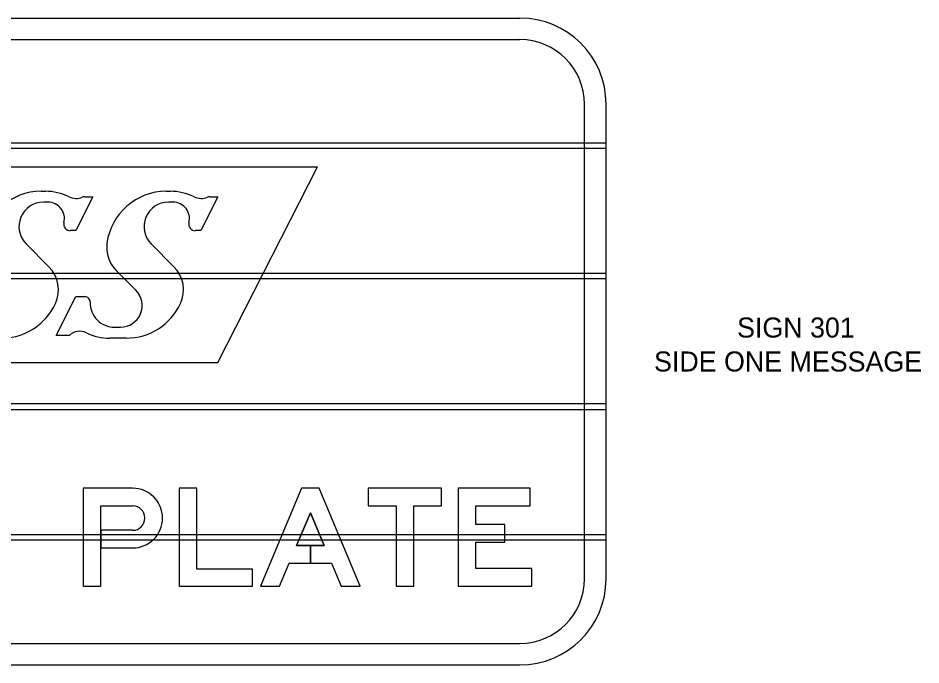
# Model space of a CAD drawing. Extents: x 319706 to 320346, y 1621790 to 1622121.
# Drawn here: x 319957 to 320020, y 1621942.3 to 1621987.5 of the extents above; entities that cross this region are included whole.
import ezdxf

# ---------------------------------------------------------------- set-up
doc = ezdxf.new("R2010")
doc.units = 0
for name, color, linetype in [('1', 7, 'Continuous'), ('40', 7, 'Continuous'), ('GSBWFill', 7, 'Continuous'), ('GSColorFill', 7, 'Continuous'), ('GSOutline', 7, 'Continuous'), ('SignPanel', 7, 'Continuous')]:
    doc.layers.add(name, color=color, linetype=linetype)

msp = doc.modelspace()

# ---------------------------------------------------------------- linework, layer by layer
at = {"layer": 'GSBWFill'}
msp.add_line((319962.741, 1621953.413), (319964.965, 1621953.413), dxfattribs=at)
for points in [[(319964.965, 1621954.644), (319961.51, 1621954.644), (319961.51, 1621947.803), (319962.741, 1621947.803), (319962.741, 1621953.413)], [(319964.965, 1621951.703), (319962.741, 1621951.703), (319962.741, 1621950.471), (319964.965, 1621950.471)]]:
    msp.add_lwpolyline(points, dxfattribs=at)
for points in [[(319973.345, 1621947.803), (319973.345, 1621949), (319969.446, 1621949), (319969.446, 1621954.644), (319968.214, 1621954.644), (319968.214, 1621947.803)], [(319978.343, 1621950.642), (319977.382, 1621950.642), (319977.382, 1621949.411), (319978.86, 1621949.411), (319979.535, 1621947.803), (319980.871, 1621947.803), (319977.998, 1621954.644), (319976.766, 1621954.644), (319973.893, 1621947.803), (319975.228, 1621947.803), (319975.904, 1621949.411), (319977.382, 1621949.411), (319977.382, 1621950.642), (319976.421, 1621950.642), (319977.382, 1621952.93)], [(319981.418, 1621953.413), (319983.368, 1621953.413), (319983.368, 1621947.803), (319984.6, 1621947.803), (319984.6, 1621953.413), (319986.55, 1621953.413), (319986.55, 1621954.644), (319981.418, 1621954.644)], [(319992.844, 1621949.034), (319988.944, 1621949.034), (319988.944, 1621950.874), (319990.962, 1621950.874), (319990.962, 1621952.106), (319988.944, 1621952.106), (319988.944, 1621953.413), (319992.741, 1621953.413), (319992.741, 1621954.644), (319987.713, 1621954.644), (319987.713, 1621947.803), (319992.844, 1621947.803)]]:
    msp.add_lwpolyline(points, close=True, dxfattribs=at)
for major_axis in [(0, 2.087), (0, 0.855)]:
    msp.add_ellipse((319964.965, 1621952.558), major_axis=major_axis, ratio=0.999994, start_param=3.141593, end_param=6.283185, dxfattribs=at)
at = {"layer": 'GSColorFill'}
msp.add_line((319962.741, 1621953.413), (319964.965, 1621953.413), dxfattribs=at)
for points in [[(319964.965, 1621954.644), (319961.51, 1621954.644), (319961.51, 1621947.803), (319962.741, 1621947.803), (319962.741, 1621953.413)], [(319964.965, 1621951.703), (319962.741, 1621951.703), (319962.741, 1621950.471), (319964.965, 1621950.471)]]:
    msp.add_lwpolyline(points, dxfattribs=at)
for points in [[(319973.345, 1621947.803), (319973.345, 1621949), (319969.446, 1621949), (319969.446, 1621954.644), (319968.214, 1621954.644), (319968.214, 1621947.803)], [(319978.343, 1621950.642), (319977.382, 1621950.642), (319977.382, 1621949.411), (319978.86, 1621949.411), (319979.535, 1621947.803), (319980.871, 1621947.803), (319977.998, 1621954.644), (319976.766, 1621954.644), (319973.893, 1621947.803), (319975.228, 1621947.803), (319975.904, 1621949.411), (319977.382, 1621949.411), (319977.382, 1621950.642), (319976.421, 1621950.642), (319977.382, 1621952.93)], [(319981.418, 1621953.413), (319983.368, 1621953.413), (319983.368, 1621947.803), (319984.6, 1621947.803), (319984.6, 1621953.413), (319986.55, 1621953.413), (319986.55, 1621954.644), (319981.418, 1621954.644)], [(319992.844, 1621949.034), (319988.944, 1621949.034), (319988.944, 1621950.874), (319990.962, 1621950.874), (319990.962, 1621952.106), (319988.944, 1621952.106), (319988.944, 1621953.413), (319992.741, 1621953.413), (319992.741, 1621954.644), (319987.713, 1621954.644), (319987.713, 1621947.803), (319992.844, 1621947.803)]]:
    msp.add_lwpolyline(points, close=True, dxfattribs=at)
for major_axis in [(0, 2.087), (0, 0.855)]:
    msp.add_ellipse((319964.965, 1621952.558), major_axis=major_axis, ratio=0.999994, start_param=3.141593, end_param=6.283185, dxfattribs=at)
at = {"layer": 'GSOutline'}
for p, q in [((319962.741, 1621953.413), (319964.965, 1621953.413)), ((319962.741, 1621950.471), (319964.965, 1621950.471))]:
    msp.add_line(p, q, dxfattribs=at)
for points in [[(319964.965, 1621954.644), (319961.51, 1621954.644), (319961.51, 1621947.803), (319962.741, 1621947.803), (319962.741, 1621950.471)], [(319964.965, 1621951.703), (319962.741, 1621951.703), (319962.741, 1621953.413)]]:
    msp.add_lwpolyline(points, dxfattribs=at)
for points in [[(319973.345, 1621947.803), (319973.345, 1621949), (319969.446, 1621949), (319969.446, 1621954.644), (319968.214, 1621954.644), (319968.214, 1621947.803)], [(319975.904, 1621949.411), (319978.86, 1621949.411), (319979.535, 1621947.803), (319980.871, 1621947.803), (319977.998, 1621954.644), (319976.766, 1621954.644), (319973.893, 1621947.803), (319975.228, 1621947.803)], [(319981.418, 1621953.413), (319983.368, 1621953.413), (319983.368, 1621947.803), (319984.6, 1621947.803), (319984.6, 1621953.413), (319986.55, 1621953.413), (319986.55, 1621954.644), (319981.418, 1621954.644)], [(319992.844, 1621949.034), (319988.944, 1621949.034), (319988.944, 1621950.874), (319990.962, 1621950.874), (319990.962, 1621952.106), (319988.944, 1621952.106), (319988.944, 1621953.413), (319992.741, 1621953.413), (319992.741, 1621954.644), (319987.713, 1621954.644), (319987.713, 1621947.803), (319992.844, 1621947.803)], [(319978.343, 1621950.642), (319977.382, 1621952.93), (319976.421, 1621950.642)]]:
    msp.add_lwpolyline(points, close=True, dxfattribs=at)
for major_axis in [(0, 2.087), (0, 0.855)]:
    msp.add_ellipse((319964.965, 1621952.558), major_axis=major_axis, ratio=0.999994, start_param=3.141593, end_param=6.283185, dxfattribs=at)
at = {"layer": 'SignPanel'}
for p, q in [((319895.646, 1621987.477), (319992.019, 1621987.477)), ((319895.646, 1621985.972), (319992.019, 1621985.972)), ((319996.537, 1621948.326), (319996.537, 1621981.453)), ((319998.043, 1621948.326), (319998.043, 1621981.453)), ((319889.623, 1621978.771), (319998.043, 1621978.771)), ((319889.623, 1621978.394), (319998.043, 1621978.394)), ((319934.55, 1621977.088), (319977.874, 1621977.088)), ((319970.908, 1621963.418), (319977.874, 1621977.088)), ((319958.58, 1621975.379), (319958.868, 1621975.379)), ((319962.194, 1621974.999), (319960.987, 1621972.63)), ((319961.624, 1621974.999), (319962.194, 1621974.999)), ((319967.315, 1621975.379), (319967.603, 1621975.379)), ((319970.927, 1621974.999), (319969.72, 1621972.63)), ((319970.357, 1621974.999), (319970.927, 1621974.999)), ((319959.061, 1621974.619), (319958.736, 1621974.619)), ((319967.795, 1621974.619), (319967.47, 1621974.619)), ((319960.987, 1621972.63), (319960.607, 1621972.63)), ((319969.72, 1621972.63), (319969.34, 1621972.63)), ((319957.527, 1621971.703), (319959.119, 1621970.111)), ((319966.262, 1621971.703), (319967.853, 1621970.111)), ((319889.623, 1621969.661), (319998.043, 1621969.661)), ((319965.188, 1621968.479), (319963.822, 1621969.846)), ((319889.623, 1621969.286), (319998.043, 1621969.286)), ((319959.628, 1621965.317), (319961.006, 1621968.024)), ((319961.006, 1621968.024), (319961.617, 1621968.024)), ((319963.704, 1621965.886), (319964.114, 1621965.886)), ((319960.551, 1621965.317), (319959.628, 1621965.317)), ((319964.523, 1621965.126), (319963.379, 1621965.126)), ((319933.543, 1621963.418), (319970.908, 1621963.418)), ((319889.623, 1621960.551), (319998.043, 1621960.551)), ((319889.623, 1621960.146), (319998.043, 1621960.146)), ((319889.623, 1621951.412), (319998.043, 1621951.412)), ((319889.623, 1621951.036), (319998.043, 1621951.036)), ((319895.082, 1621943.808), (319992.019, 1621943.808)), ((319895.113, 1621942.302), (319992.019, 1621942.302))]:
    msp.add_line(p, q, dxfattribs=at)
for centre, radius, start, end in [((319992.019, 1621981.454), 6.023, 0, 90), ((319992.019, 1621981.454), 4.517, 0, 90), ((319958.58, 1621971.201), 4.177, 90, 172.30892), ((319958.868, 1621971.581), 3.797, 64.08957, 90), ((319961.025, 1621976.021), 1.139, 244.08957, 292.03474), ((319961.623, 1621974.543), 0.456, 90, 112.03474), ((319967.314, 1621971.201), 4.177, 90, 172.30892), ((319967.602, 1621971.581), 3.797, 64.08957, 90), ((319969.759, 1621976.021), 1.139, 244.08957, 292.03474), ((319970.357, 1621974.543), 0.456, 90, 112.03474), ((319958.735, 1621972.91), 1.709, 90, 225), ((319959.061, 1621973.48), 1.139, 345.69149, 90), ((319967.469, 1621972.91), 1.709, 90, 225), ((319967.795, 1621973.48), 1.139, 345.69149, 90), ((319960.606, 1621973.085), 0.456, 165.69149, 270), ((319969.34, 1621973.085), 0.456, 165.69149, 270), ((319965.432, 1621971.455), 2.278, 172.30892, 225), ((319957.508, 1621968.499), 2.278, 334.94996, 45), ((319966.242, 1621968.499), 2.278, 334.94996, 45), ((319964.113, 1621967.404), 1.519, 270, 45), ((319955.788, 1621969.303), 4.177, 270, 334.94996), ((319961.616, 1621967.642), 0.38, 358.66645, 90), ((319963.704, 1621967.594), 1.709, 178.66645, 270), ((319964.521, 1621969.303), 4.177, 270, 334.94996), ((319961.277, 1621964.54), 1.063, 64.37946, 133.18921), ((319963.379, 1621968.923), 3.797, 244.37946, 270), ((319992.019, 1621948.325), 4.517, 270, 0), ((319992.019, 1621948.325), 6.023, 270, 0)]:
    msp.add_arc(centre, radius, start, end, dxfattribs=at)

# ---------------------------------------------------------------- texts
at = {"layer": '1'}
msp.add_text('SIDE ONE MESSAGE', height=1.4, dxfattribs=at).set_placement((320001.39, 1621962.794))
at = {"layer": '40'}
msp.add_text('SIGN 301', height=1.4, dxfattribs=at).set_placement((320007.191, 1621965.164))

doc.saveas('drawing.dxf')
